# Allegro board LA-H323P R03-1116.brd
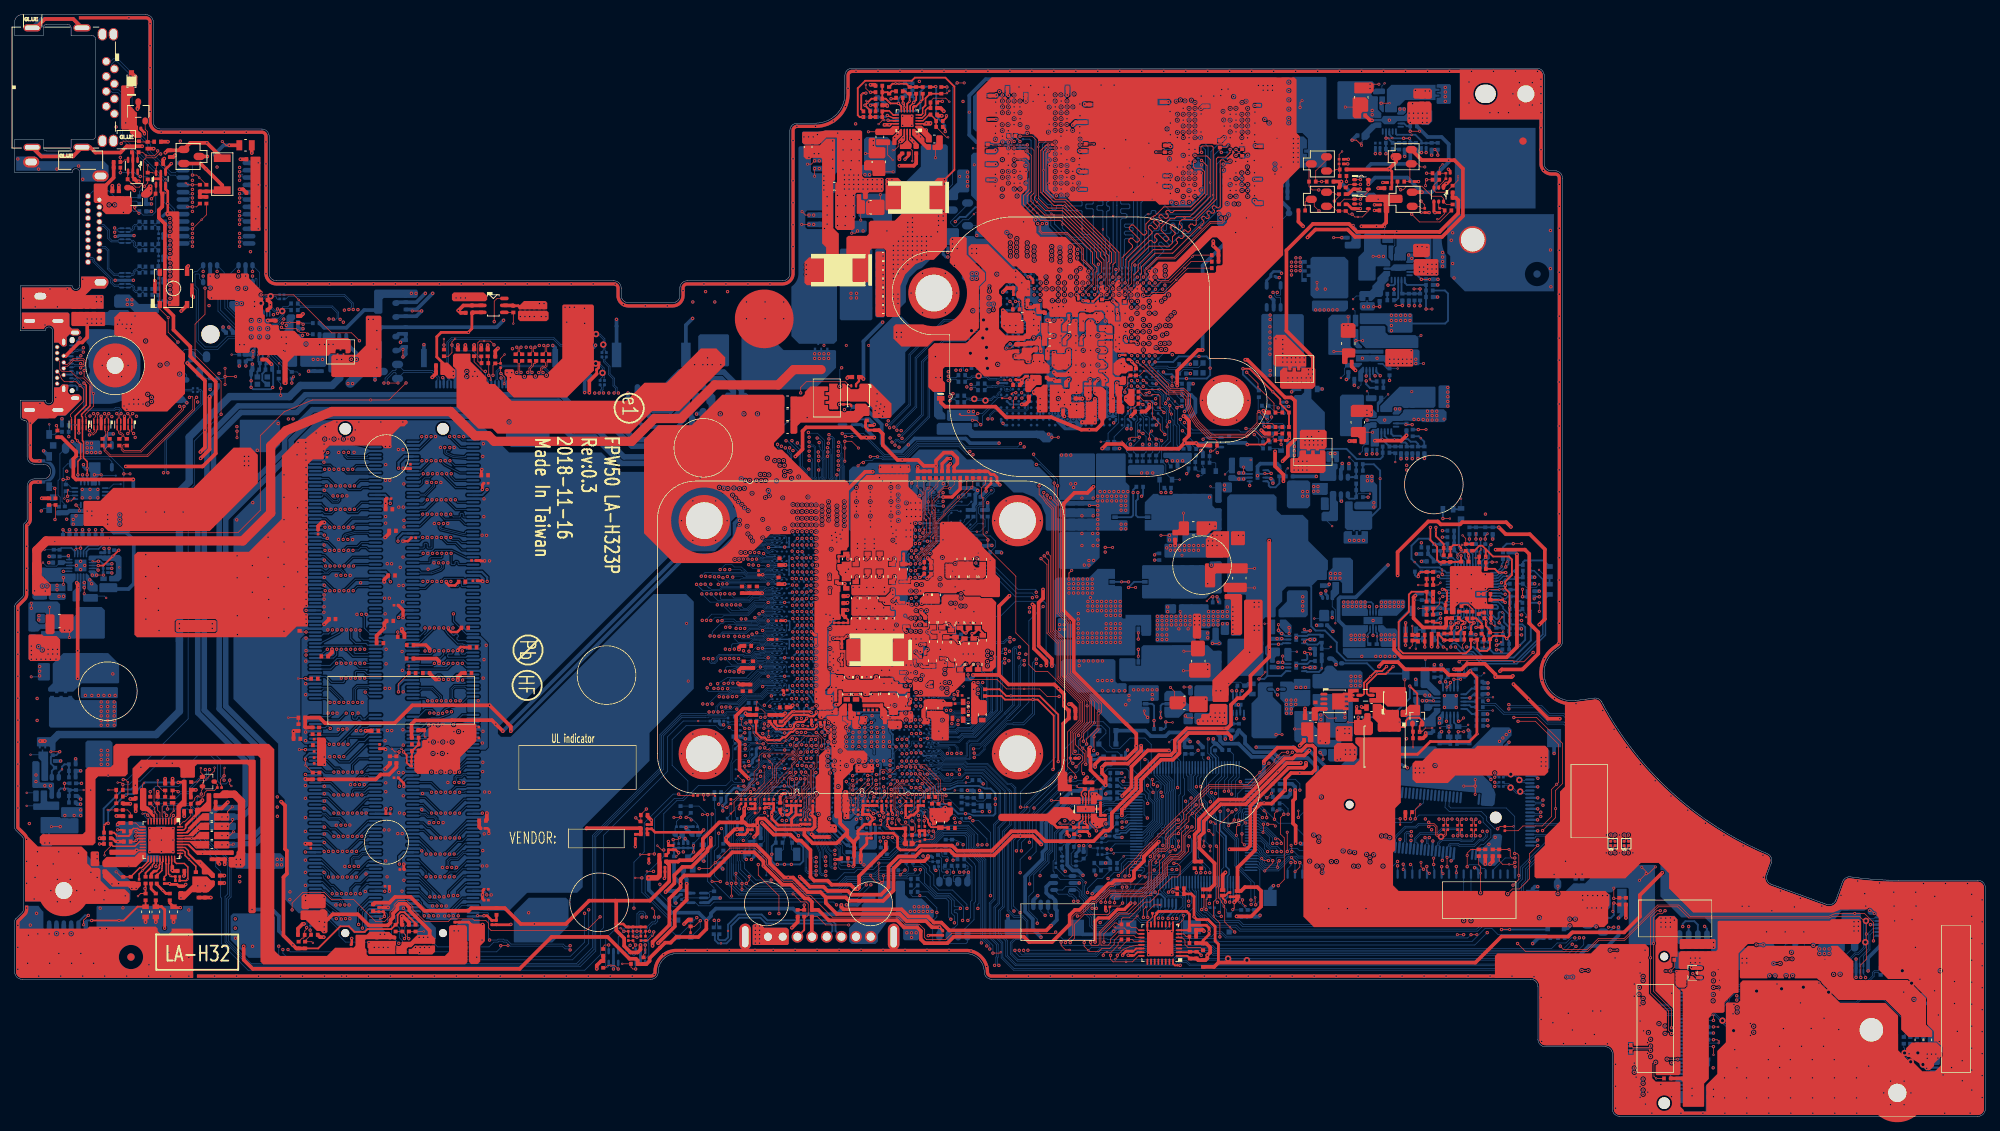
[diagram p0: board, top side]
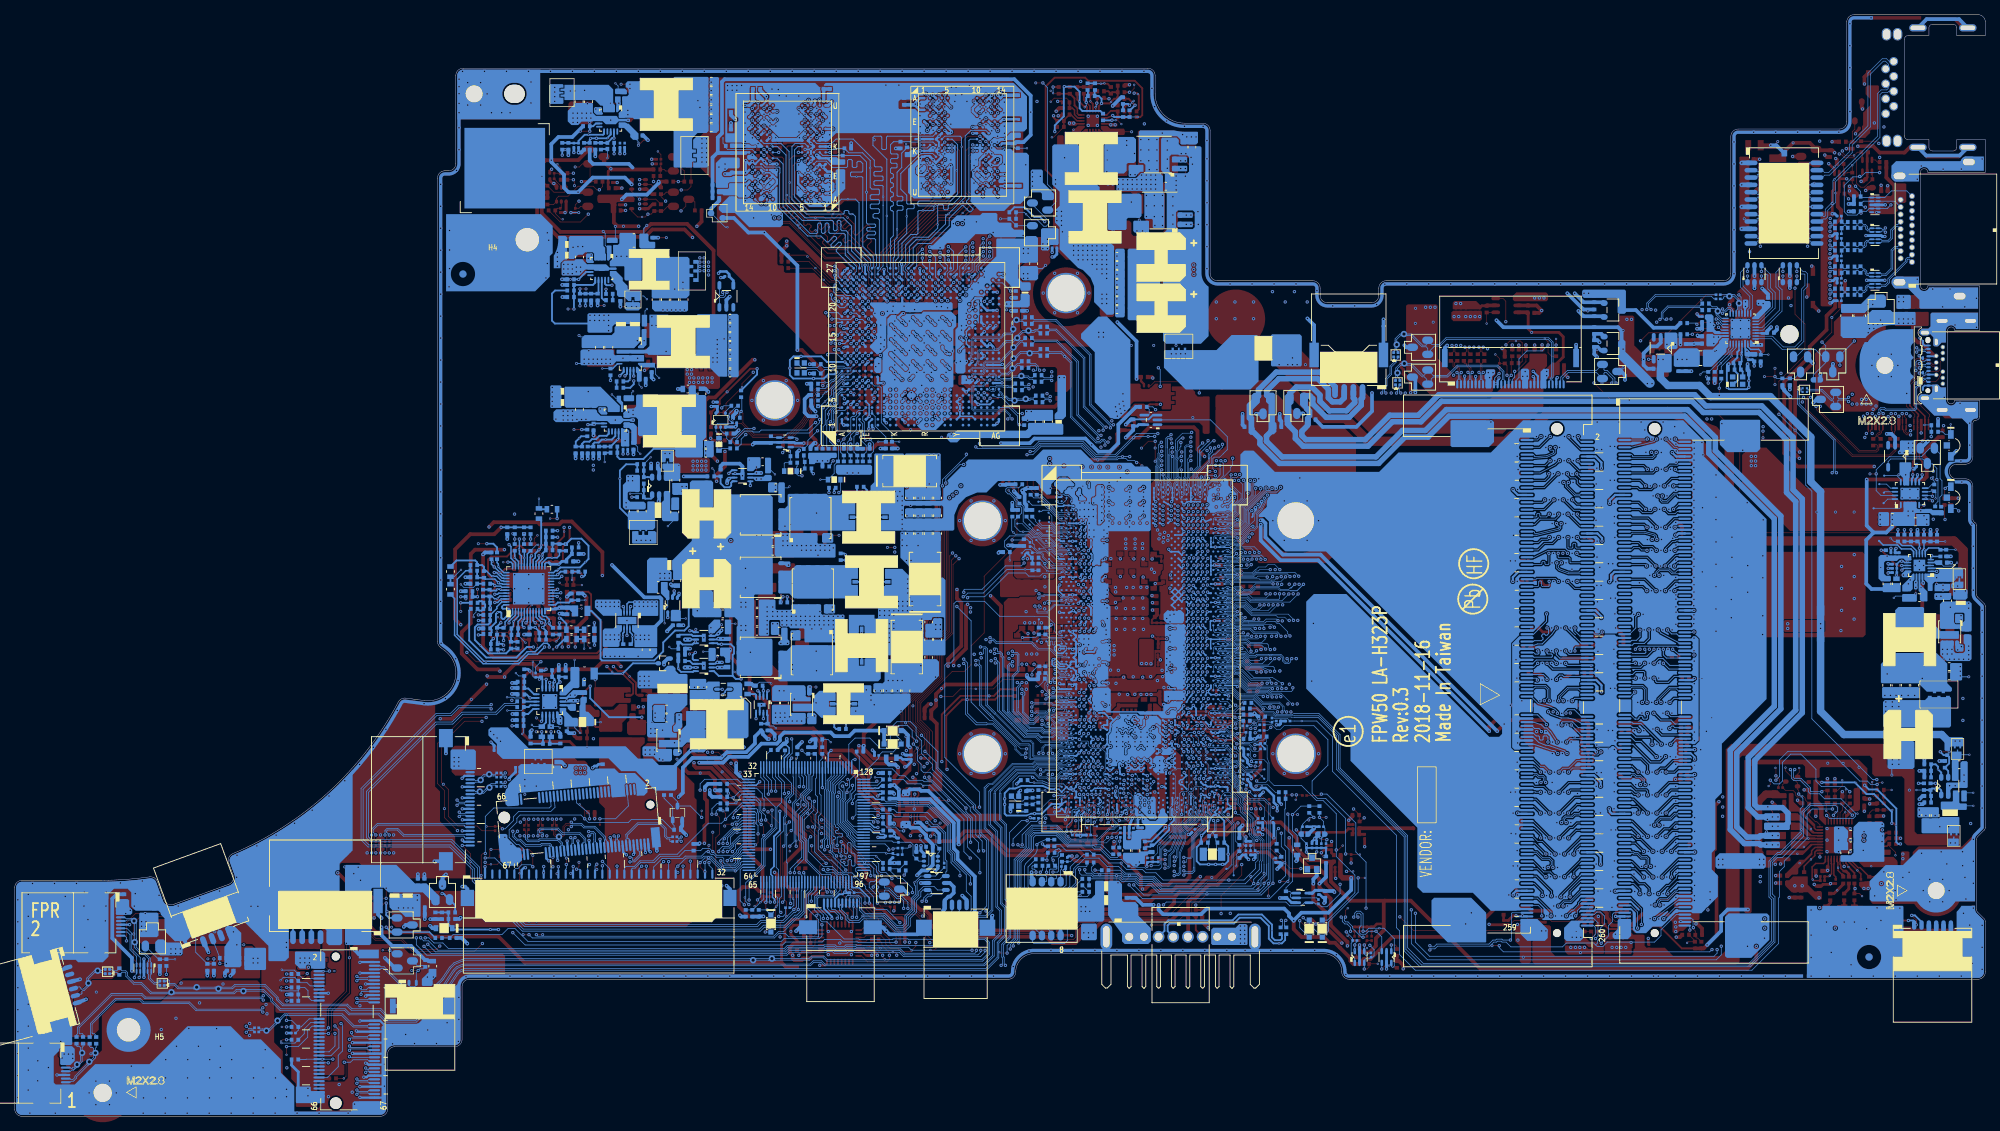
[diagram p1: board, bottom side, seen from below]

Outline 268.7 x 150.3 mm; copper layers: TOP, VCC, IN1, IN2, GND, BOTTOM. Coordinates in mm from the lower left corner of the outline.
Outline path: 0,149.3 0,147.45 3.89,147.45 3.89,148.5 arc(4.04,148.86) 4.39,149 7.19,149 arc(7.54,148.86) 7.69,148.5 7.69,147.45 10.54,147.45 arc(10.89,147.31) 11.04,146.95 11.04,133.75 arc(10.89,133.4) 10.54,133.25 7.69,133.25 7.69,132.2 arc(7.54,131.85) 7.19,131.7 4.39,131.7 arc(4.04,131.85) 3.89,132.2 3.89,133.25 0,133.25 0,128.8 7.85,128.8 arc(8.35,129.3) 8.85,128.8 8.85,113.3 arc(8.35,112.8) 7.85,113.3 0.78,113.3 0.78,107.2 4.17,107.2 arc(4.67,107.7) 5.17,107.2 5.17,97.7 arc(4.67,97.2) 4.17,97.7 0.78,97.7 0.78,95.47 arc(0.93,95.11) 1.29,94.97 arc(1.58,94.86) 1.7,94.57 1.7,89.97 arc(1.99,89.26) 2.7,88.97 3.9,88.97 arc(4.9,87.97) 3.9,86.97 2.7,86.97 arc(1.99,86.68) 1.7,85.97 1.7,81.47 arc(1.63,81.22) 1.45,81.04 arc(1.27,80.85) 1.2,80.6 1.2,71.21 arc(1.16,71.02) 1.05,70.85 0.15,69.95 arc(0.04,69.78) 0,69.59 0,39.41 arc(0.04,39.22) 0.15,39.05 1.05,38.15 arc(1.16,37.98) 1.2,37.79 1.2,28.21 arc(1.16,28.02) 1.05,27.85 0.15,26.95 arc(0.04,26.78) 0,26.59 0,19.7 arc(0.29,18.99) 1,18.7 86.75,18.7 arc(87.46,18.99) 87.75,19.7 arc(88.48,21.47) 90.25,22.2 129.7,22.2 arc(131.47,21.47) 132.2,19.7 arc(132.49,18.99) 133.2,18.7 206.7,18.7 arc(207.41,18.41) 207.7,17.7 207.7,10.5 arc(207.99,9.79) 208.7,9.5 216.85,9.5 arc(217.56,9.21) 217.85,8.5 217.85,1 arc(218.14,0.29) 218.85,0 267.7,0 arc(268.41,0.29) 268.7,1 268.7,31.2 arc(268.41,31.91) 267.7,32.2 256.85,32.2 arc(253.58,32.32) 250.32,32.67 arc(249.66,32.54) 249.23,32.02 248.32,29.51 arc(247.81,28.95) 247.04,28.92 239.52,31.65 arc(238.96,32.17) 238.93,32.93 239.52,34.57 arc(239.5,35.31) 238.97,35.83 arc(225.9,44.24) 216.39,56.54 arc(215.97,56.96) 215.38,57.06 212.83,56.73 arc(208.83,59.05) 210.04,63.52 210.66,63.99 arc(210.95,64.35) 211.05,64.79 211.05,128 arc(210.76,128.71) 210.05,129 209.55,129 arc(208.84,129.29) 208.55,130 208.55,142 arc(208.26,142.71) 207.55,143 114.2,143 arc(113.49,142.71) 113.2,142 113.2,139.5 arc(112.03,136.67) 109.2,135.5 106.7,135.5 arc(105.99,135.21) 105.7,134.5 105.7,115 arc(105.41,114.29) 104.7,114 91.7,114 arc(90.99,113.71) 90.7,113 90.7,112 arc(90.41,111.29) 89.7,111 83.7,111 arc(82.99,111.29) 82.7,112 82.7,113 arc(82.41,113.71) 81.7,114 35.7,114 arc(34.99,114.29) 34.7,115 34.7,133.7 arc(34.41,134.41) 33.7,134.7 19.9,134.7 arc(19.19,134.99) 18.9,135.7 18.9,149.3 arc(18.61,150.01) 17.9,150.3 1,150.3 arc(0.29,150.01) 0,149.3

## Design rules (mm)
net group CLK_PCIE_N3: nets CLK_PCIE_N3 CLK_PCIE_P3
net group CNVI_WGR_CLK_D: nets CNVI_WGR_CLK_DN CNVI_WGR_CLK_DP
net group CNVI_WGR_DATA0_D: nets CNVI_WGR_DATA0_DN CNVI_WGR_DATA0_DP
net group CNVI_WGR_DATA1_D: nets CNVI_WGR_DATA1_DN CNVI_WGR_DATA1_DP
net group CNVI_WT_CLK_D: nets CNVI_WT_CLK_DN CNVI_WT_CLK_DP
net group CNVI_WT_DATA0_D: nets CNVI_WT_DATA0_DN CNVI_WT_DATA0_DP
net group CNVI_WT_DATA1_D: nets CNVI_WT_DATA1_DN CNVI_WT_DATA1_DP
net group D_MIC_: nets D_MIC_CLK D_MIC_DATA
net group DDR5-CLK1: nets FB_CLK1 FB_CLK#1
net group DDR5-WCK01: nets FB_WCK01 FB_WCK01#
net group DDR5-WCK23: nets FB_WCK23 FB_WCK23#
net group DDR5-WCK45: nets FB_WCK45 FB_WCK45#
net group DDR5-WCK67: nets FB_WCK67 FB_WCK67#
net group DDR-CLK0: nets FB_CLK0 FB_CLK#0
net group DIFFPAIR0: nets SPK_L+_CONN SPK_L-_CONN
net group DIFFPAIR1: nets SPK_R+_CONN SPK_R-_CONN
net group DIFFPAIR2: nets EC_SMB_CK2 EC_SMB_DA2
net group DIFFPAIR3: nets EC_SMB_CK1 EC_SMB_DA1
net group EDP_AUX: nets EDP_AUXN EDP_AUXP
net group EDP_AUX_C: nets EDP_AUXN_C EDP_AUXP_C
net group EDP_TX0: nets EDP_TXN0 EDP_TXP0
net group EDP_TX0_C: nets EDP_TXN0_C EDP_TXP0_C
net group EDP_TX1: nets EDP_TXN1 EDP_TXP1
net group EDP_TX1_C: nets EDP_TXN1_C EDP_TXP1_C
net group HDMI_CLK: nets HDMI_CLKN HDMI_CLKP
net group HDMI_R_CLK: nets HDMI_R_CLKN HDMI_R_CLKP
net group HDMI_R_TX_0: nets HDMI_R_TX_N0 HDMI_R_TX_P0
net group HDMI_R_TX_1: nets HDMI_R_TX_N1 HDMI_R_TX_P1
net group HDMI_R_TX_2: nets HDMI_R_TX_N2 HDMI_R_TX_P2
net group HDMI_TX_0: nets HDMI_TX_N0 HDMI_TX_P0
net group HDMI_TX_1: nets HDMI_TX_N1 HDMI_TX_P1
net group HDMI_TX_2: nets HDMI_TX_N2 HDMI_TX_P2
net group HOST_DP1_0: nets HOST_DP1_N0 HOST_DP1_P0
net group HOST_DP1_1: nets HOST_DP1_N1 HOST_DP1_P1
net group HOST_DP1_2: nets HOST_DP1_N2 HOST_DP1_P2
net group HOST_DP1_3: nets HOST_DP1_N3 HOST_DP1_P3
net group HOST_DP1_CTRL_: nets HOST_DP1_CTRL_CLK HOST_DP1_CTRL_DATA
net group I2C0__TP: nets I2C0_SCL_TP I2C0_SDA_TP
net group LAN_MDI0: nets LAN_MDIN0 LAN_MDIP0
net group LAN_MDI1: nets LAN_MDIN1 LAN_MDIP1
net group LAN_MDI2: nets LAN_MDIN2 LAN_MDIP2
net group LAN_MDI3: nets LAN_MDIN3 LAN_MDIP3
net group PCH_RTCX: nets PCH_RTCX1 PCH_RTCX2
net group PCH_SMB: nets PCH_SMBCLK PCH_SMBDATA
net group PCIEPCIE_CRX_DTX_13: nets PCIE_CRX_DTX_N13 PCIE_CRX_DTX_P13
net group PCIEPCIE_CRX_DTX_14: nets PCIE_CRX_DTX_N14 PCIE_CRX_DTX_P14
net group PCIEPCIE_CTX_C_DRX_13: nets PCIE_CTX_C_DRX_N13 PCIE_CTX_C_DRX_P13
net group PCIEPCIE_CTX_C_DRX_14: nets PCIE_CTX_C_DRX_N14 PCIE_CTX_C_DRX_P14
net group PCIEPCIE_CTX_DRX_13: nets PCIE_CTX_DRX_N13 PCIE_CTX_DRX_P13
net group PCIEPCIE_CTX_DRX_14: nets PCIE_CTX_DRX_N14 PCIE_CTX_DRX_P14
net group PCIEPCIE_RCOMP: nets PCIE_RCOMPN PCIE_RCOMPP
net group PECI: nets EC_PECI H_PECI
net group RJ45_MDI0: nets RJ45_MDIN0 RJ45_MDIP0
net group RJ45_MDI1: nets RJ45_MDIN1 RJ45_MDIP1
net group RJ45_MDI2: nets RJ45_MDIN2 RJ45_MDIP2
net group RJ45_MDI3: nets RJ45_MDIN3 RJ45_MDIP3
net group S-10: nets PLT_RST_VGA_HOLD# PLT_RST_VGA_MON#
net group SATA_CRX_C_DTX_0: nets SATA_CRX_C_DTX_N0 SATA_CRX_C_DTX_P0
net group SATA_CRX_DTX_0: nets SATA_CRX_DTX_N0 SATA_CRX_DTX_P0
net group SATA_CTX_C_DRX_0: nets SATA_CTX_C_DRX_N0 SATA_CTX_C_DRX_P0
net group SATA_CTX_DRX_0: nets SATA_CTX_DRX_N0 SATA_CTX_DRX_P0
net group SMB: nets SMBCLK SMBDATA
net group SML0: nets SML0CLK SML0DATA
net group SML1: nets SML1CLK SML1DATA
net group TP_: nets TP_CLK TP_DATA
net group UART: nets UART_2_CRXD_DTXD UART_2_CTXD_DRXD
net group USB2USB20_3_C: nets USB20_N3_C USB20_P3_C
net group USB2USB20_6: nets USB20_N6 USB20_P6
net group USB3_CRX_DTX_1: nets USB3_CRX_DTX_N1 USB3_CRX_DTX_P1
net group USB3_CRX_DTX_2: nets USB3_CRX_DTX_N2 USB3_CRX_DTX_P2
net group USB3_CTX_C_DRX_1: nets USB3_CTX_C_DRX_N1 USB3_CTX_C_DRX_P1
net group USB3_CTX_C_DRX_2: nets USB3_CTX_C_DRX_N2 USB3_CTX_C_DRX_P2
net group USB3_CTX_DRX_1: nets USB3_CTX_DRX_N1 USB3_CTX_DRX_P1
net group USB3_CTX_DRX_2: nets USB3_CTX_DRX_N2 USB3_CTX_DRX_P2
net group USB3USB3_CRX_DTX_3: nets USB3_CRX_DTX_N3 USB3_CRX_DTX_P3
net group USB3USB3_CRX_DTX_4: nets USB3_CRX_DTX_N4 USB3_CRX_DTX_P4
net group USB3USB3_CTX_C_DRX_3: nets USB3_CTX_C_DRX_N3 USB3_CTX_C_DRX_P3
net group USB3USB3_CTX_C_DRX_4: nets USB3_CTX_C_DRX_N4 USB3_CTX_C_DRX_P4
net group USB3USB3_CTX_DRX_3: nets USB3_CTX_DRX_N3 USB3_CTX_DRX_P3
net group USB3USB3_CTX_DRX_4: nets USB3_CTX_DRX_N4 USB3_CTX_DRX_P4
net group USB20_1: nets USB20_N1 USB20_P1
net group USB20_1_R: nets USB20_N1_R USB20_P1_R
net group USB20_2: nets USB20_N2 USB20_P2
net group USB20_2_R: nets USB20_N2_R USB20_P2_R
net group USB20_3: nets USB20_N3 USB20_P3
net group USB20_4_R: nets USB20_N4_R USB20_P4_R
net group USB20_5: nets USB20_N5 USB20_P5
net group USB20_5_R: nets USB20_N5_R USB20_P5_R
net group USB20_7: nets USB20_N7 USB20_P7
net group USB20_7_R: nets USB20_N7_R USB20_P7_R
net group USB20_N10: nets USB20_N10 USB20_P10
net group W15: nets CC1 CC2
net group CNVI: nets CNVI_BRI_DT CNVI_BRI_DT_R CNVI_BRI_RSP CNVI_BRI_RSP_R CNVI_RF_RESET_N CNVI_RF_RESET_R_N CNVI_RGI_DT CNVI_RGI_DT_R CNVI_RGI_RSP CNVI_RGI_RSP_R
net group CRYSTAL: nets XTAL_OUT XTALIN XTLI XTLO
net group DDR_M0(CLK-CMD): nets DDR_M0_ACT# DDR_M0_ALERT# DDR_M0_BA0 DDR_M0_BA1 DDR_M0_BG0 DDR_M0_BG1 DDR_M0_MA0 DDR_M0_MA1 DDR_M0_MA2 DDR_M0_MA3 DDR_M0_MA4 DDR_M0_MA5 DDR_M0_MA6 DDR_M0_MA7 DDR_M0_MA8 DDR_M0_MA9 DDR_M0_MA10 DDR_M0_MA11 DDR_M0_MA12 DDR_M0_MA13 DDR_M0_MA14_WE# DDR_M0_MA15_CAS# DDR_M0_MA16_RAS# DDR_M0_PAR
net group DDR_M0(CLK-CTRL): nets DDR_M0_CKE0 DDR_M0_CKE1 DDR_M0_CS#0 DDR_M0_CS#1 DDR_M0_ODT0 DDR_M0_ODT1
net group DDR_M0(CLK-DQS): nets DDR_M0_CLK0 DDR_M0_CLK1 DDR_M0_CLK#0 DDR_M0_CLK#1
net group DDR_M0-DQ0: nets DDR_M0_D0 DDR_M0_D1 DDR_M0_D2 DDR_M0_D3 DDR_M0_D4 DDR_M0_D5 DDR_M0_D6 DDR_M0_D7 DDR_M0_DQS0 DDR_M0_DQS#0
net group DDR_M0-DQ1: nets DDR_M0_D8 DDR_M0_D9 DDR_M0_D10 DDR_M0_D11 DDR_M0_D12 DDR_M0_D13 DDR_M0_D14 DDR_M0_D15 DDR_M0_DQS1 DDR_M0_DQS#1
net group DDR_M0-DQ2: nets DDR_M0_D16 DDR_M0_D17 DDR_M0_D18 DDR_M0_D19 DDR_M0_D20 DDR_M0_D21 DDR_M0_D22 DDR_M0_D23 DDR_M0_DQS2 DDR_M0_DQS#2
net group DDR_M0-DQ3: nets DDR_M0_D24 DDR_M0_D25 DDR_M0_D26 DDR_M0_D27 DDR_M0_D28 DDR_M0_D29 DDR_M0_D30 DDR_M0_D31 DDR_M0_DQS3 DDR_M0_DQS#3
net group DDR_M0-DQ4: nets DDR_M0_D32 DDR_M0_D33 DDR_M0_D34 DDR_M0_D35 DDR_M0_D36 DDR_M0_D37 DDR_M0_D38 DDR_M0_D39 DDR_M0_DQS4 DDR_M0_DQS#4
net group DDR_M0-DQ5: nets DDR_M0_D40 DDR_M0_D41 DDR_M0_D42 DDR_M0_D43 DDR_M0_D44 DDR_M0_D45 DDR_M0_D46 DDR_M0_D47 DDR_M0_DQS5 DDR_M0_DQS#5
net group DDR_M0-DQ6: nets DDR_M0_D48 DDR_M0_D49 DDR_M0_D50 DDR_M0_D51 DDR_M0_D52 DDR_M0_D53 DDR_M0_D54 DDR_M0_D55 DDR_M0_DQS6 DDR_M0_DQS#6
net group DDR_M0-DQ7: nets DDR_M0_D56 DDR_M0_D57 DDR_M0_D58 DDR_M0_D59 DDR_M0_D60 DDR_M0_D61 DDR_M0_D62 DDR_M0_D63 DDR_M0_DQS7 DDR_M0_DQS#7
net group DDR_M1(CLK-CMD): nets DDR_M1_ACT# DDR_M1_ALERT# DDR_M1_BA0 DDR_M1_BA1 DDR_M1_BG0 DDR_M1_BG1 DDR_M1_MA0 DDR_M1_MA1 DDR_M1_MA2 DDR_M1_MA3 DDR_M1_MA4 DDR_M1_MA5 DDR_M1_MA6 DDR_M1_MA7 DDR_M1_MA8 DDR_M1_MA9 DDR_M1_MA10 DDR_M1_MA11 DDR_M1_MA12 DDR_M1_MA13 DDR_M1_MA14_WE# DDR_M1_MA15_CAS# DDR_M1_MA16_RAS# DDR_M1_PAR
net group DDR_M1(CLK-CTRL): nets DDR_M1_CKE0 DDR_M1_CKE1 DDR_M1_CS#0 DDR_M1_CS#1 DDR_M1_ODT0 DDR_M1_ODT1
net group DDR_M1(CLK-DQS): nets DDR_M1_CLK0 DDR_M1_CLK1 DDR_M1_CLK#0 DDR_M1_CLK#1
net group DDR_M1-DQ0: nets DDR_M1_D0 DDR_M1_D1 DDR_M1_D2 DDR_M1_D3 DDR_M1_D4 DDR_M1_D5 DDR_M1_D6 DDR_M1_D7 DDR_M1_DQS0 DDR_M1_DQS#0
net group DDR_M1-DQ1: nets DDR_M1_D8 DDR_M1_D9 DDR_M1_D10 DDR_M1_D11 DDR_M1_D12 DDR_M1_D13 DDR_M1_D14 DDR_M1_D15 DDR_M1_DQS1 DDR_M1_DQS#1
net group DDR_M1-DQ2: nets DDR_M1_D16 DDR_M1_D17 DDR_M1_D18 DDR_M1_D19 DDR_M1_D20 DDR_M1_D21 DDR_M1_D22 DDR_M1_D23 DDR_M1_DQS2 DDR_M1_DQS#2
net group DDR_M1-DQ3: nets DDR_M1_D24 DDR_M1_D25 DDR_M1_D26 DDR_M1_D27 DDR_M1_D28 DDR_M1_D29 DDR_M1_D30 DDR_M1_D31 DDR_M1_DQS3 DDR_M1_DQS#3
net group DDR_M1-DQ4: nets DDR_M1_D32 DDR_M1_D33 DDR_M1_D34 DDR_M1_D35 DDR_M1_D36 DDR_M1_D37 DDR_M1_D38 DDR_M1_D39 DDR_M1_DQS4 DDR_M1_DQS#4
net group DDR_M1-DQ5: nets DDR_M1_D40 DDR_M1_D41 DDR_M1_D42 DDR_M1_D43 DDR_M1_D44 DDR_M1_D45 DDR_M1_D46 DDR_M1_D47 DDR_M1_DQS5 DDR_M1_DQS#5
net group DDR_M1-DQ6: nets DDR_M1_D48 DDR_M1_D49 DDR_M1_D50 DDR_M1_D51 DDR_M1_D52 DDR_M1_D53 DDR_M1_D54 DDR_M1_D55 DDR_M1_DQS6 DDR_M1_DQS#6
net group DDR_M1-DQ7: nets DDR_M1_D56 DDR_M1_D57 DDR_M1_D58 DDR_M1_D59 DDR_M1_D60 DDR_M1_D61 DDR_M1_D62 DDR_M1_D63 DDR_M1_DQS7 DDR_M1_DQS#7
net group DGPU_PCIE-12: nets PEG_CRX_C_GTX_N5 PEG_CRX_C_GTX_N6 PEG_CRX_C_GTX_N7 PEG_CRX_C_GTX_N8 PEG_CRX_C_GTX_P5 PEG_CRX_C_GTX_P6 PEG_CRX_C_GTX_P7 PEG_CRX_C_GTX_P8 PEG_CRX_GTX_N5 PEG_CRX_GTX_N6 PEG_CRX_GTX_N7 PEG_CRX_GTX_N8 PEG_CRX_GTX_P5 PEG_CRX_GTX_P6 PEG_CRX_GTX_P7 PEG_CRX_GTX_P8 PEG_CTX_C_GRX_N5 PEG_CTX_C_GRX_N6 PEG_CTX_C_GRX_N7 PEG_CTX_C_GRX_N8 PEG_CTX_C_GRX_P5 PEG_CTX_C_GRX_P6 PEG_CTX_C_GRX_P7 PEG_CTX_C_GRX_P8 PEG_CTX_GRX_N5 PEG_CTX_GRX_N6 PEG_CTX_GRX_N7 PEG_CTX_GRX_N8 PEG_CTX_GRX_P5 PEG_CTX_GRX_P6 PEG_CTX_GRX_P7 PEG_CTX_GRX_P8
net group GDDR5_CMD: nets FB_CMD0 FB_CMD1 FB_CMD2 FB_CMD3 FB_CMD4 FB_CMD5 FB_CMD6 FB_CMD7 FB_CMD8 FB_CMD9 FB_CMD10 FB_CMD11 FB_CMD12 FB_CMD13 FB_CMD14 FB_CMD15 FB_CMD16 FB_CMD17 FB_CMD18 FB_CMD19 FB_CMD20 FB_CMD21 FB_CMD22 FB_CMD23 FB_CMD24 FB_CMD25 FB_CMD26 FB_CMD27 FB_CMD28 FB_CMD29 FB_CMD30 FB_CMD31
net group GDDR5_DQ: nets FB_D0 FB_D1 FB_D2 FB_D3 FB_D4 FB_D5 FB_D6 FB_D7 FB_D8 FB_D9 FB_D10 FB_D11 FB_D12 FB_D13 FB_D14 FB_D15 FB_D16 FB_D17 FB_D18 FB_D19 FB_D20 FB_D21 FB_D22 FB_D23 FB_D24 FB_D25 FB_D26 FB_D27 FB_D28 FB_D29 FB_D30 FB_D31 FB_D32 FB_D33 FB_D34 FB_D35 FB_D36 FB_D37 FB_D38 FB_D39 FB_D40 FB_D41 FB_D42 FB_D43 FB_D44 FB_D45 FB_D46 FB_D47 FB_D48 FB_D49 FB_D50 FB_D51 FB_D52 FB_D53 FB_D54 FB_D55 FB_D56 FB_D57 FB_D58 FB_D59 FB_D60 FB_D61 FB_D62 FB_D63
net group GDDR5_EDC/DBI: nets FB_DBI0 FB_DBI1 FB_DBI2 FB_DBI3 FB_DBI4 FB_DBI5 FB_DBI6 FB_DBI7 FB_EDC0 FB_EDC1 FB_EDC2 FB_EDC3 FB_EDC4 FB_EDC5 FB_EDC6 FB_EDC7
net group GUARDRING: nets PCH_XTAL24_IN PCH_XTAL24_IN_R PCH_XTAL24_OUT PCH_XTAL24_OUT_R XCLK_BIASREF
net group HDA: nets EC_BEEP# HDA_RST# HDA_RST#_R HDA_SDIN0 HDA_SDIN0_R HDA_SDOUT HDA_SDOUT_R HDA_SPKR HDA_SYNC HDA_SYNC_R N36039462 PC_BEEP PC_BEEP_R
net group KB: nets KSI0 KSI1 KSI2 KSI3 KSI4 KSI5 KSI6 KSI7 KSO0 KSO1 KSO2 KSO3 KSO4 KSO5 KSO6 KSO7 KSO8 KSO9 KSO10 KSO11 KSO12 KSO13 KSO14 KSO15 KSO16 KSO17
net group PCIE-12: nets PCIE_CRX_C_DTX_N9 PCIE_CRX_C_DTX_P9 PCIE_CRX_DTX_N9 PCIE_CRX_DTX_N10 PCIE_CRX_DTX_N15 PCIE_CRX_DTX_N16 PCIE_CRX_DTX_P9 PCIE_CRX_DTX_P10 PCIE_CRX_DTX_P15 PCIE_CRX_DTX_P16 PCIE_CTX_C_DRX_N9 PCIE_CTX_C_DRX_N10 PCIE_CTX_C_DRX_N15 PCIE_CTX_C_DRX_N16 PCIE_CTX_C_DRX_P9 PCIE_CTX_C_DRX_P10 PCIE_CTX_C_DRX_P15 PCIE_CTX_C_DRX_P16 PCIE_CTX_DRX_N9 PCIE_CTX_DRX_N10 PCIE_CTX_DRX_N15 PCIE_CTX_DRX_N16 PCIE_CTX_DRX_P9 PCIE_CTX_DRX_P10 PCIE_CTX_DRX_P15 PCIE_CTX_DRX_P16
net group PLATFORM CLK: nets CLK_PCIE_N1 CLK_PCIE_N2 CLK_PCIE_P1 CLK_PCIE_P2 CLK_PEG_N0 CLK_PEG_P0
net group S-12: nets EC_VCCST_PG_R H_PROCHOT#_R H_THERMTRIP# PLT_RST# TP_SMBCLK
net group S-15: nets CLK_PCI0 CLK_PCI_LPC CLKIN_XTAL_LCP DGPU_HOLD_RST# EC_KBRST# EC_SPI_CLK EMMC_RCOMP HDA_BIT_CLK HDA_BIT_CLK_R HDMI_CTRL_CLK HOST_SPI_0_CLK I2CA_SCL I2CB_SCL I2CC_SCL I2CS_SCL INT_MIC INT_MIC_R MIC2-VREFO N36039105 PLT_RST#_PCH PLT_RST#_SSD PLT_RST_VGA# PLUG_IN# SCL_CHG SD_RCOMP SM_RCOMP0 SM_RCOMP1 SM_RCOMP2 SPK_L+ SPK_L- SPK_R+ SPK_R- SYS_RESET# USB2_COMP
net group S-20: nets DDR_DRAMRST#
net group S-25: nets EDP_COMP
net group S-30: nets HP_OUTL HP_OUTL_R HP_OUTR HP_OUTR_R HPOUT_L HPOUT_R
net group SMBUS: nets EC_SMB_CK1_R EC_SMB_DA1_R I2CA_SDA I2CB_SDA I2CC_SDA I2CS_SDA SDA_CHG
net group SPI: nets EC_SPI_CS0# EC_SPI_SI EC_SPI_SO HOST_DP1_HPD HOST_SPI_0_CLK_R HOST_SPI_0_CLK_R_TPM HOST_SPI_0_CS0# HOST_SPI_0_CS2# HOST_SPI_0_CS2#_TPM HOST_SPI_0_HOLD# HOST_SPI_0_SI HOST_SPI_0_SI_R HOST_SPI_0_SI_TPM HOST_SPI_0_SIO2 HOST_SPI_0_SIO3 HOST_SPI_0_SO HOST_SPI_0_SO_R HOST_SPI_0_SO_TPM HOST_SPI_0_WP#
net group SVID: nets N19950078 N19950080 SOC_SVID_ALERT# VR_ALERT# VR_SVID_CLK VR_SVID_DATA
net group TP_SMB: nets TP_SMBDATA
net group USB2.0: nets USB20_N4 USB20_N6_R USB20_P4 USB20_P6_R
net group VR: nets RGND_AUXI RGND_SA VSEN_GT
net group W12: nets CFG_RCOMP CPU_POPIRCOMP PCH_OPIRCOMP
net group W20: nets +0.6V_B_VREFDQ +0.6V_DDR_VREFCA +0.6V_VREFCA
nets with their own width: min track width 0.203; nets +3V_SMBUS
nets with their own width: min track width 0.254; nets ECAGND
nets with their own width: min track width 0.305; nets +1.35VS_VRAM
nets with their own width: min track width 0.508; nets 3V_SN +1.8V_PG +3V_LID +3V_PRIM +3V_SPI +3VALW +3VALW_EC +3VL +3VS +3VS_DGPU_AON +3VS_TOUCH +5VALW +5VS +5VS_KBL +5VS_TOUCH +FAN1 +V_DAC GND GNDA LANGND XGND
nets with their own width: min track width 1.016; nets +1.0VS_DGPU +3VS_CAMERA
nets with their own width: min track width 1.524; nets +3VS_SSD +3VS_WLAN +LCDVDD

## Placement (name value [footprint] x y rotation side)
C11  220P_0402_50V7K  [C_0402]  92.24 95.07 180 bottom
C12  220P_0402_50V7K  [C_0402]  95.3 95.07 0 bottom
C13  220P_0402_50V7K  [C_0402]  96.91 94.06 180 bottom
C14  220P_0402_50V7K  [C_0402]  100.1 94.08 0 bottom
C18  0.1U_0201_10V6K  [C_0201]  16.62 134.83 0 top
C19  10P_0402_50V8J  [C_0402]  19.02 132.96 0 top
C117  680P_0402_50V7K  [C_0402]  61.45 103.7 90 top
C118  68P_0402_50V8J  [C_0402]  60.43 103.7 90 top
C140  470P_0402_50V8J  [C_0402]  261.17 10.12 270 bottom
C153  0.01U_0402_16V7K  [C_0402]  258.47 10.82 270 bottom
C154  0.01U_0402_16V7K  [C_0402]  257.58 10.82 270 bottom
C155  0.01U_0402_16V7K  [C_0402]  260.26 10.83 270 bottom
C156  0.01U_0402_16V7K  [C_0402]  259.37 10.83 270 bottom
C174  330U_2.5V_M  [C_MP2VLPS330MC4R2]  10.52 54.89 90 bottom
C193  100P_0402_50V8J  [C_0402]  176.13 37.17 270 bottom
C554  100P_0402_50V8J  [C_0402]  185.72 64.42 270 bottom
C557  680P_0402_50V7K  [C_0402]  184.7 64.42 270 bottom
C570  10U_0402_6.3V6M  [C_0402]  186.74 64.42 270 bottom
C575  10U_0402_6.3V6M  [C_0402]  183.69 64.42 270 bottom
C593  220P_0402_50V7K  [C_0402]  62.64 103.72 90 top
C594  220P_0402_50V7K  [C_0402]  64.5 103.7 90 top
C4801  10U_0402_6.3V6M  [C_0402]  238.87 20.8 270 bottom
C5181  0.1U_0402_25V6  [C_0402]  230.03 3.69 0 bottom
C5182  100P_0402_50V8J  [C_0402]  230.03 2.68 0 bottom
C5183  0.1U_0402_25V6  [C_0402]  228.33 22.22 90 top
C5184  100P_0402_50V8J  [C_0402]  230.03 3.69 0 top
C5185  10P_0402_50V8J  [C_0402]  220.35 8.83 180 top
C5186  10P_0402_50V8J  [C_0402]  220.35 9.71 180 top
C5214  0.1U_0402_16V7K  [C_0402]  239.76 20.8 270 bottom
C5221  .1U_0402_16V7K  [C_0402]  58.36 102.45 180 top
C5222  4.7U_0402_6.3V6M  [C_0402]  58.36 101.48 180 top
C5228  100P_0402_50V8J  [C_0402]  18.13 132.94 270 top
C5230  0.1U_0402_25V6  [C_0402]  171.97 93.15 180 top
C5231  0.1U_0402_16V7K  [C_0402]  62.34 111.54 270 top
C5232  0.1U_0402_16V7K  [C_0402]  62.42 109.62 180 top
C5233  10U_0402_6.3V6M  [C_0402]  187.75 64.42 270 bottom
CA5  0.1U 16V K X7R 0402  [C_0402]  15.98 35.12 90 top
CA6  4.7U_0402_6.3V6M  [C_0402]  15.1 35.12 90 top
CA7  10U_0402_6.3V6M  [C_0402]  14.21 35.12 90 top
CA8  4.7U_0402_6.3V6M  [C_0402]  25.98 33.32 270 top
CA9  0.1U 16V K X7R 0402  [C_0402]  14.8 40.94 270 top
CA10  0.1U 16V K X7R 0402  [C_0402]  25.09 29.85 90 top
CA11  0.1U 16V K X7R 0402  [C_0402]  22.68 31.4 270 top
CA12  0.1U 16V K X7R 0402  [C_0402]  27.96 31.83 180 top
CA13  0.1U 16V K X7R 0402  [C_0402]  11.3 33.35 0 top
CA15  1U_0201_6.3V6K  [C_0201]  20.39 31.75 90 top
CA16  1U_0201_6.3V6K  [C_0201]  22.5 32.72 180 top
CA19  10U_0402_6.3V6M  [C_0402]  27.75 35.98 270 top
CA20  0.1U 16V K X7R 0402  [C_0402]  26.86 35.98 270 top
CA21  10U_0402_6.3V6M  [C_0402]  26.48 42.02 0 top
CA22  0.1U 16V K X7R 0402  [C_0402]  24.97 41.79 90 top
CA23  0.1U 16V K X7R 0402  [C_0402]  24.02 41.62 180 top
CA24  100P_0603_50V7  [C_0603]  17.85 28.61 270 top
CA25  100P_0603_50V7  [C_0603]  19.24 28.61 270 top
CA26  100P_0603_50V7  [C_0603]  21.66 28.61 270 top
CA27  10U_0402_6.3V6M  [C_0402]  24.71 33.32 270 top
CA28  10U_0402_6.3V6M  [C_0402]  19.5 42.69 90 top
CA29  10U_0402_6.3V6M  [C_0402]  14.89 37.49 0 top
CA30  10U_0402_6.3V6M  [C_0402]  15.82 31.77 90 top
CA31  2.2U_0201_6.3V6M  [C_0201]  16.97 31.75 90 top
CA32  4.7U_0402_6.3V6M  [C_0402]  17.42 43.4 180 top
CA33  0.1U 16V K X7R 0402  [C_0402]  17.42 42.38 180 top
CA34  22P 50V J NPO 0402  [C_0402]  20.51 45.38 270 top
CA36  4.7U_0402_6.3V6M  [C_0402]  23.1 44.54 0 top
CA37  0.1U 16V K X7R 0402  [C_0402]  23.1 43.53 0 top
CA39  10U_0402_6.3V6M  [C_0402]  23.14 33.48 180 top
CA41  10P_0402_50V8J  [C_0402]  21.53 44.47 90 top
CA42  0.1U 16V K X7R 0402  [C_0402]  15.82 40.94 270 top
CA43  0.1U 16V K X7R 0402  [C_0402]  14.76 44.53 180 top
CA44  0.1U 16V K X7R 0402  [C_0402]  14.76 43.64 180 top
CA45  10U_0402_6.3V6M  [C_0402]  28.64 35.98 270 top
CA46  10U_0402_6.3V6M  [C_0402]  26.49 42.9 0 top
CA47  10U_0402_6.3V6M  [C_0402]  13.32 35.12 90 top
CA48  1U_0201_6.3V6K  [C_0201]  22.5 32.15 180 top
CC7  1U_0201_6.3V6K  [C_0201]  91.17 37.21 270 bottom
CC8  0.1U_0201_10V6K  [C_0201]  126.55 25.29 270 top
CC9  68P_0201_25V8  [C_0201]  125.98 34.08 180 bottom
CC10  1U_0201_6.3V6K  [C_0201]  92.53 39.52 0 bottom
CC11  1U_0201_6.3V6K  [C_0201]  90.83 39.52 180 bottom
CC12  27P_0402_50V J  [C_0402]  130.77 43.44 90 bottom
CC13  27P_0402_50V J  [C_0402]  130.77 42.58 270 bottom
CC14  0.1U_0201_10V6K  [C_0201]  90.91 30.83 270 bottom
CC15  5.6P_0402_50V  [C_0402]  106 37.34 0 bottom
CC16  5.6P_0402_50V  [C_0402]  104.7 37.34 180 bottom
CC19  0.1U_0201_10V6K  [C_0201]  236 12.09 180 bottom
CC20  0.1U_0201_10V6K  [C_0201]  236 11.51 180 bottom
CC27  10U_0402_6.3V6M  [C_0402]  112.1 71.98 90 top
CC28  10U_0402_6.3V6M  [C_0402]  110.18 57.89 0 top
CC29  1U_0201_6.3V6K  [C_0201]  111.12 72.73 90 top
CC30  1U_0201_6.3V6K  [C_0201]  112.35 76.98 270 top
CC31  1U_0201_6.3V6K  [C_0201]  111.15 70.87 90 top
CC32  1U_0201_6.3V6K  [C_0201]  109.81 55.64 270 top
CC33  1U_0201_6.3V6K  [C_0201]  115.49 54.37 180 top
CC34  1U_0201_6.3V6K  [C_0201]  110.92 59.54 0 top
CC35  1U_0201_6.3V6K  [C_0201]  110.92 60.12 0 top
CC36  1U_0201_6.3V6K  [C_0201]  115.38 53.77 180 top
CC37  10U_0402_6.3V6M  [C_0402]  100.42 64.18 180 top
CC38  10U_0402_6.3V6M  [C_0402]  104.34 55.8 0 top
CC39  10U_0402_6.3V6M  [C_0402]  99.4 62.08 270 top
CC40  10U_0402_6.3V6M  [C_0402]  100.67 62.08 270 top
CC41  10U_0402_6.3V6M  [C_0402]  100.3 57.99 90 top
CC42  10U_0402_6.3V6M  [C_0402]  101.2 72.3 270 top
CC43  1U_0201_6.3V6K  [C_0201]  103.87 67.61 0 top
CC44  1U_0201_6.3V6K  [C_0201]  101.43 74.44 270 top
CC45  1U_0201_6.3V6K  [C_0201]  103.95 65.07 180 top
CC46  1U_0201_6.3V6K  [C_0201]  105.34 58.15 180 top
CC48  1U_0201_6.3V6K  [C_0201]  120.63 53.77 90 top
CC49  .1U_0201_6.3V7K  [C_0201]  86.85 39.22 90 top
CC50  1U_0201_6.3V6K  [C_0201]  88.08 33.99 0 top
CC51  0.1U_0201_10V6K  [C_0201]  114.24 34.63 0 bottom
CC55  1U_0201_6.3V6K  [C_0201]  120 53.77 90 top
CC57  0.1U_0402_16V7K  [C_0402]  116.19 94.18 90 bottom
CC58  10U_0402_6.3V6M  [C_0402]  99.27 58.01 90 top
CC59  10U_0402_6.3V6M  [C_0402]  104.29 76.13 270 top
CC60  10U_0402_6.3V6M  [C_0402]  104.16 73.53 270 top
CC61  1U_0201_6.3V6K  [C_0201]  115.85 55.44 90 top
CC62  0.1U_0201_10V6K  [C_0201]  119.27 53.8 180 top
CC63  1U_0201_6.3V6K  [C_0201]  110.96 54.43 90 top
CC67  1U_0201_6.3V6K  [C_0201]  99.93 39.68 270 top
CC68  1U_0201_6.3V6K  [C_0201]  116.99 55.44 90 top
CC71  0.1U_0201_6.3V6K  [C_0201]  109.23 54.1 180 top
CC72  1U_0201_6.3V6K  [C_0201]  113.27 54.97 0 top
CC73  1U_0201_6.3V6K  [C_0201]  112.47 43.07 0 top
CC74  1U_0201_6.3V6K  [C_0201]  116.19 38.54 270 top
CC76  1U_0201_6.3V6K  [C_0201]  116.42 55.44 90 top
CC80  1U_0201_6.3V6K  [C_0201]  128.23 56.29 180 top
CC81  47U_0805_6.3V6M  [C_0805]  125.1 54.83 90 top
CC82  22U_0603_6.3V6M  [C_0603]  129.33 54.12 0 top
CC86  1U_0201_6.3V6K  [C_0201]  126.35 55.1 90 top
CC87  1U_0201_6.3V6K  [C_0201]  115.55 38.78 90 bottom
CC88  0.1U_0402_25V6  [C_0402]  115.12 100.86 180 top
CC89  0.1U_0201_6.3V  [C_0201]  116.02 94.25 0 top
CC90  0.1U_0201_6.3V  [C_0201]  110.38 55.64 270 top
CC91  1U_0201_6.3V6K  [C_0201]  117.56 55.44 90 top
CC94  1000P_0402_50V7K  [C_0402]  146.92 44.65 90 top
CC95  10P_0402_50V8J  [C_0402]  145.91 44.65 90 top
CC96  0.1U_0201_6.3V  [C_0201]  143.33 45.74 0 top
CC97  1U_0201_6.3V6K  [C_0201]  143.49 39.43 270 top
CC98  1U_0201_6.3V6K  [C_0201]  145.7 39.43 270 top
CC102  1U_0201_6.3V6K  [C_0201]  112.47 43.71 0 top
CC103  1U_0201_6.3V6K  [C_0201]  114.92 38.78 90 bottom
CC111  22U_0603_6.3V6M  [C_0603]  113.45 56.88 90 top
CC112  22U_0603_6.3V6M  [C_0603]  114.72 56.88 90 top
CC115  22U_0603_6.3V6M  [C_0603]  117.08 36.98 270 bottom
CC116  22U_0603_6.3V6M  [C_0603]  115.81 36.98 270 bottom
CC117  1U_0201_6.3V6K  [C_0201]  113.01 97.72 270 top
CC122  100P_0402_50V8J  [C_0402]  200.52 36.42 270 top
CC123  100P_0402_50V8J  [C_0402]  201.53 36.42 270 top
CC127  0.1U_0201_10V6K  [C_0201]  171.28 114.6 0 bottom
CC134  22U_0603_6.3V6M  [C_0603]  129.33 56.53 0 top
CC140  22U_0603_6.3V6M  [C_0603]  182.61 64.35 270 bottom
CC141  0.1U_0201_10V6K  [C_0201]  112.58 55.54 180 top
CC142  1U_0201_6.3V6K  [C_0201]  133.12 87.59 270 top
CC144  22P 50V J NPO 0402  [C_0402]  149.39 46.84 0 bottom
CC154  3.3P_0402_50V8J  [C_0402]  254.43 19.3 90 bottom
CC159  0.1U_0402_25V6  [C_0402]  47.6 22.5 0 top
CC163  0.1U_0402_25V6  [C_0402]  181.47 64.36 270 bottom
CC170  22U_0805_25V6M  [C_0805]  18.91 108.39 90 bottom
CC171  22U_0805_25V6M  [C_0805]  17.13 108.39 90 bottom
CC184  0.22U_0201_6.3V  [C_0201]  178.99 37.5 180 bottom
CC185  0.22U_0201_6.3V  [C_0201]  178.99 38.13 180 bottom
CC186  0.22U_0201_6.3V  [C_0201]  194.83 39.11 90 top
CC187  0.22U_0201_6.3V  [C_0201]  195.4 39.11 90 top
CC256  22P 50V J NPO 0402  [C_0402]  95.41 43.33 0 bottom
CC261  0.1U_0201_6.3V  [C_0201]  145.13 39.43 270 top
CC269  0.1U_0201_10V6K  [C_0201]  113.88 53.79 90 top
CC270  0.1U_0201_10V6K  [C_0201]  129.18 57.42 180 top
CC274  1U_0201_6.3V6K  [C_0201]  148.7 40.49 90 top
CC275  0.1U_0201_6.3V  [C_0201]  148.06 43.37 270 top
CC276  0.22U_0402_16V7K  [C_0402]  129.47 98.32 180 bottom
CC277  0.22U_0402_16V7K  [C_0402]  132.27 99.08 180 bottom
CC278  0.22U_0402_16V7K  [C_0402]  132.27 99.97 180 bottom
CC279  0.22U_0402_16V7K  [C_0402]  129.6 100.22 180 bottom
CC280  0.22U_0402_16V7K  [C_0402]  129.6 101.11 180 bottom
CC281  0.22U_0402_16V7K  [C_0402]  129.47 97.43 180 bottom
CC282  0.22U_0402_16V7K  [C_0402]  131.38 103.02 180 bottom
CC283  0.22U_0402_16V7K  [C_0402]  131.38 102.13 180 bottom
CC288  0.22U_0201_6.3V  [C_0201]  197.3 39.11 90 top
CC289  0.22U_0201_6.3V  [C_0201]  196.73 39.11 90 top
CC290  0.22U_0201_6.3V  [C_0201]  198.64 39.11 90 top
CC291  0.22U_0201_6.3V  [C_0201]  199.21 39.11 90 top
CC292  100P_0402_50V8J  [C_0402]  131.09 77.82 90 bottom
CC293  0.1U_0402_16V7K  [C_0402]  124.94 75.61 180 top
CC295  10P_0402_50V8J  [C_0402]  127.81 36.84 90 bottom
CC296  22P_0201_25V8  [C_0201]  94.81 53.93 0 bottom
CC297  10P_0402_50V8J  [C_0402]  95.99 34.49 90 bottom
CC298  0.1U_0402_16V7K  [C_0402]  101.15 51.5 180 bottom
CC299  0.1U_0402_16V7K  [C_0402]  97.99 51.81 0 bottom
CC300  0.1U_0402_16V7K  [C_0402]  95.36 30.7 270 bottom
CC301  0.1U_0402_16V7K  [C_0402]  121.45 39.26 0 top
CC302  0.1U_0402_16V7K  [C_0402]  122.36 38.37 180 top
CC303  0.1U_0402_16V7K  [C_0402]  128.16 65.75 90 bottom
CC312  22P 50V J NPO 0402  [C_0402]  100.24 54.82 0 bottom
CC314  1.8P_0402_50V8J  [C_0402]  114.46 35.58 0 top
CC315  1.8P_0402_50V8J  [C_0402]  90.04 30.74 270 bottom
CC316  1U_0201_6.3V6K  [C_0201]  110.42 53.77 180 top
CC317  47U_0603_6.3V6M  [C_0603]  131.94 54.06 90 top
CC318  4.7U_0603_10V6K  [C_0603]  126.22 39.39 90 top
CC319  1U_0201_6.3V6K  [C_0201]  124.72 39.9 0 top
CC320  4.7U_0402_6.3V6M  [C_0402]  113.65 36.99 270 bottom
CC321  1U_0201_6.3V6K  [C_0201]  86.22 39.22 90 top
CC323  1U_0201_6.3V6K  [C_0201]  89.14 36.37 90 top
CC324  0.1U_0201_10V6K  [C_0201]  91.8 37.21 270 bottom
CC325  4.7U_0402_6.3V6M  [C_0402]  110.98 38.11 90 top
CC326  0.1U_0201_10V6K  [C_0201]  36.14 112.1 0 bottom
CC327  0.1U_0201_10V6K  [C_0201]  36.14 111.53 0 bottom
CC328  1U_0201_6.3V6K  [C_0201]  113.27 55.54 0 top
CC329  22U_0603_6.3V6M  [C_0603]  129.33 55.33 0 top
CC331  1U_0201_6.3V6K  [C_0201]  88.08 33.36 0 top
CC332  1U_0201_6.3V6K  [C_0201]  100.57 39.68 270 top
CC333  1U_0201_6.3V6K  [C_0201]  113.27 56.11 0 top
CC334  1U_0201_6.3V6K  [C_0201]  112.47 41.8 0 top
CC335  1U_0201_6.3V6K  [C_0201]  112.47 42.44 0 top
CC336  1U_0201_6.3V6K  [C_0201]  116.82 38.54 270 top
CC337  1U_0201_6.3V6K  [C_0201]  116.15 38.06 0 bottom
CC338  1U_0201_6.3V6K  [C_0201]  116.15 38.69 0 bottom
CC339  1U_0201_6.3V6K  [C_0201]  146.29 39.43 270 top
CC341  1U_0201_6.3V6K  [C_0201]  148.06 40.49 90 top
CC342  1U_0201_6.3V6K  [C_0201]  89.77 36.37 90 top
CC343  1U_0201_6.3V6K  [C_0201]  112.58 54.97 180 top
CC346  10U_0402_6.3V6M  [C_0402]  143.72 54.33 0 top
CC347  10U_0402_6.3V6M  [C_0402]  112.34 68.12 0 top
CC348  10U_0402_6.3V6M  [C_0402]  112.09 70.97 0 top
CC349  10U_0402_6.3V6M  [C_0402]  112.06 70.02 0 top
CC350  10U_0402_6.3V6M  [C_0402]  112.02 69.07 0 top
CC351  1U_0201_6.3V6K  [C_0201]  115.06 54.97 180 top
CC352  0.1U_0201_10V6K  [C_0201]  172.66 92.22 0 top
CC353  0.1U_0201_10V6K  [C_0201]  170.84 94.62 180 bottom
CC354  0.1U_0402_16V7K  [C_0402]  92.16 26.83 270 top
CC355  100P_0402_50V8J  [C_0402]  26.65 99.77 90 bottom
CC356  10U_0402_6.3V6M  [C_0402]  100.19 72.3 270 top
CC357  10U_0402_6.3V6M  [C_0402]  99.17 72.3 270 top
CC358  10U_0402_6.3V6M  [C_0402]  143.72 55.34 0 top
CC359  0.1U_0402_16V7K  [C_0402]  85.38 41.1 0 top
CC360  0.1U_0201_10V6K  [C_0201]  154.25 30.51 0 bottom
CC361  0.1U_0201_10V6K  [C_0201]  149.31 28.58 180 top
CC362  0.1U_0201_10V6K  [C_0201]  148.19 37.38 90 bottom
CC363  0.1U_0201_10V6K  [C_0201]  150.88 49.23 0 bottom
CC364  0.1U_0201_10V6K  [C_0201]  143.96 48.85 0 top
CC365  0.1U_0201_10V6K  [C_0201]  148.95 35.87 270 bottom
CC366  0.1U_0201_10V6K  [C_0201]  84.63 37.89 90 top
CD1  0.1U_0201_10V6K  [C_0201]  65.06 26.14 90 top
CD2  2.2U_0201_6.3V6M  [C_0201]  65.69 26.14 90 top
CD3  10U_0402_6.3V6M  [C_0402]  49.41 21.5 90 top
CD4  10U_0402_6.3V6M  [C_0402]  50.43 21.5 90 top
CD5  1U_0201_6.3V6K  [C_0201]  49.39 24.32 270 top
CD6  1U_0201_6.3V6K  [C_0201]  51.8 24.32 270 top
CD7  10U_0402_6.3V6M  [C_0402]  53.16 22.5 0 top
CD8  10U_0402_6.3V6M  [C_0402]  52.32 22.5 180 top
CD9  1U_0201_6.3V6K  [C_0201]  41.92 27.98 90 top
CD10  0.1U_0402_25V6  [C_0402]  38.84 66.24 90 top
CD11  0.1U_0201_10V6K  [C_0201]  54.69 49.06 180 top
CD12  2.2U_0201_6.3V6M  [C_0201]  54.68 48.42 180 top
CD13  0.1U_0201_10V6K  [C_0201]  52.3 69.72 180 top
CD14  0.1U_0201_10V6K  [C_0201]  54.71 47.77 180 top
CD15  0.022U_0402_25V7K  [C_0402]  54.11 52.68 0 top
CD16  10U_0402_6.3V6M  [C_0402]  61.84 66.65 180 top
CD17  10U_0402_6.3V6M  [C_0402]  51.86 73.79 180 top
CD18  10U_0402_6.3V6M  [C_0402]  61.46 72.94 180 top
CD19  10U_0402_6.3V6M  [C_0402]  41.82 62.76 0 top
CD20  10U_0402_6.3V6M  [C_0402]  62.29 60.47 180 top
CD21  10U_0402_6.3V6M  [C_0402]  43.75 67.84 180 top
CD22  10U_0402_6.3V6M  [C_0402]  62.98 63.98 180 top
CD23  10U_0402_6.3V6M  [C_0402]  51.62 67.58 180 top
CD24  1U_0201_6.3V6K  [C_0201]  49.76 50.74 270 top
CD25  1U_0201_6.3V6K  [C_0201]  51.72 46.2 0 top
CD26  1U_0201_6.3V6K  [C_0201]  50.49 31.39 0 top
CD27  1U_0201_6.3V6K  [C_0201]  51.2 41.3 180 top
CD28  1U_0201_6.3V6K  [C_0201]  42.57 89.94 180 top
CD29  1U_0201_6.3V6K  [C_0201]  41.37 79.43 90 top
CD30  1U_0201_6.3V6K  [C_0201]  63.54 39.3 0 top
CD31  1U_0201_6.3V6K  [C_0201]  64.58 29.49 180 top
CD60  0.1U_0201_10V6K  [C_0201]  49.64 27.92 90 top
CD61  2.2U_0201_6.3V6M  [C_0201]  50.27 28.51 270 top
CD62  10U_0402_6.3V6M  [C_0402]  61.37 25.31 0 top
CD63  10U_0402_6.3V6M  [C_0402]  61.37 24.36 0 top
CD64  1U_0201_6.3V6K  [C_0201]  61.53 23.6 0 top
CD65  1U_0201_6.3V6K  [C_0201]  60 25.9 90 top
CD66  10U_0402_6.3V6M  [C_0402]  39.6 27.8 90 top
CD67  10U_0402_6.3V6M  [C_0402]  40.87 27.8 90 top
CD68  1U_0201_6.3V6K  [C_0201]  57.07 23.68 270 top
CD69  0.1U_0201_10V6K  [C_0201]  41.42 51.46 180 top
CD70  2.2U_0201_6.3V6M  [C_0201]  41.43 48.15 180 top
CD71  0.1U_0201_10V6K  [C_0201]  40.37 37.18 270 top
CD72  0.1U_0201_10V6K  [C_0201]  41.42 49.78 180 top
CD73  10U_0402_6.3V6M  [C_0402]  55.66 60.47 0 top
CD74  10U_0402_6.3V6M  [C_0402]  53.44 62.46 0 top
CD75  10U_0402_6.3V6M  [C_0402]  53.47 64.3 0 top
CD76  10U_0402_6.3V6M  [C_0402]  49.59 52.6 180 top
CD77  10U_0402_6.3V6M  [C_0402]  51.99 79.88 180 top
CD78  10U_0402_6.3V6M  [C_0402]  38.94 51.51 180 top
CD79  10U_0402_6.3V6M  [C_0402]  50.26 64.56 180 top
CD80  10U_0402_6.3V6M  [C_0402]  51.49 82.82 180 top
CD81  0.1U_0201_10V6K  [C_0201]  41.42 48.94 180 top
CD82  0.022U_0402_25V7K  [C_0402]  39.6 54.39 180 top
CD83  1U_0201_6.3V6K  [C_0201]  64.56 86.37 180 top
CD84  1U_0201_6.3V6K  [C_0201]  51.32 84.28 180 top
CD85  1U_0201_6.3V6K  [C_0201]  54.67 78.93 180 top
CD86  1U_0201_6.3V6K  [C_0201]  62.48 73.06 0 top
CD87  1U_0201_6.3V6K  [C_0201]  52.52 33.68 0 top
CD88  1U_0201_6.3V6K  [C_0201]  63.29 51.63 180 top
CD89  1U_0201_6.3V6K  [C_0201]  53.96 88.96 270 top
CD90  1U_0201_6.3V6K  [C_0201]  63.27 53.1 180 top
CD92  0.1U_0402_25V6  [C_0402]  52.23 65.43 0 top
CD93  10U_0402_6.3V6M  [C_0402]  64.54 87.47 180 top
CD94  1U_0201_6.3V6K  [C_0201]  62.3 75.84 0 top
CD95  10U_0402_6.3V6M  [C_0402]  63.34 40.35 0 top
CD96  1U_0201_6.3V6K  [C_0201]  64.58 30.98 180 top
CD97  1U_0201_6.3V6K  [C_0201]  51.16 24.32 270 top
CD98  1U_0201_6.3V6K  [C_0201]  45.87 22.84 90 top
CD99  1U_0201_6.3V6K  [C_0201]  60.64 25.9 90 top
CD100  1U_0201_6.3V6K  [C_0201]  61.53 22.96 0 top
CE24  0.01U_0402_25V7K  [C_0402]  242.43 20.8 270 bottom
CG1  0.1U_0201_10V6K  [C_0201]  68.94 110.31 270 top
CG2  4.7U_0402_6.3V6M  [C_0402]  78.71 102.71 0 top
CG3  0.1U_0201_10V6K  [C_0201]  78.77 101.87 0 top
CG4  1U_0201_6.3V6K  [C_0201]  69.58 110.31 270 top
CG8  0.1U_0402_16V7K  [C_0402]  20.51 112.03 180 bottom
CG9  0.1U_0402_16V7K  [C_0402]  20.51 112.92 180 bottom
CG10  0.1U_0402_16V7K  [C_0402]  20.51 115.08 180 bottom
CG11  0.1U_0402_16V7K  [C_0402]  20.51 115.97 180 bottom
CG12  0.1U_0402_16V7K  [C_0402]  20.51 121.18 180 bottom
CG13  0.1U_0402_16V7K  [C_0402]  20.51 122.07 180 bottom
CG14  0.1U_0402_16V7K  [C_0402]  20.51 118.13 180 bottom
CG15  0.1U_0402_16V7K  [C_0402]  20.51 119.02 180 bottom
CG46  0.1U_0402_16V7K  [C_0402]  13.32 125.29 90 top
CG47  4.7U_0402_6.3V6M  [C_0402]  14.21 125.29 90 top
CG71  180 +-5% 0402  [R_0402]  17.03 119.03 270 bottom
CG72  180 +-5% 0402  [R_0402]  17.03 112.02 90 bottom
CG73  180 +-5% 0402  [R_0402]  17.03 115.98 270 bottom
CG74  180 +-5% 0402  [R_0402]  17.03 122.08 270 bottom
CG75  1U_0201_6.3V6K  [C_0201]  70.21 110.31 270 top
CG76  1U_0201_6.3V6K  [C_0201]  71.55 110.29 270 top
CG77  1U_0201_6.3V6K  [C_0201]  72.18 110.29 270 top
CG78  1U_0201_6.3V6K  [C_0201]  70.85 110.29 270 top
CK1  0.1U_0201_10V6K  [C_0201]  147.07 48.7 90 bottom
CK2  0.1U_0201_10V6K  [C_0201]  146.46 48.71 90 bottom
CK3  0.1U_0201_10V6K  [C_0201]  165.72 29.95 90 top
CK4  0.1U_0402_25V6  [C_0402]  159.61 49.45 90 bottom
CK5  0.1U_0402_16V7K  [C_0402]  172.47 43.58 180 bottom
CK8  4.7U_0402_6.3V6M  [C_0402]  150.3 44.19 180 bottom
CK9  22P 50V J NPO 0402  [C_0402]  159.51 51.43 180 bottom
CK10  0.1U_0402_25V6  [C_0402]  150.3 39.96 180 bottom
CK11  0.1U_0201_10V6K  [C_0201]  149.93 38.23 180 bottom
CL1  0.01U_0402_16V7K  [C_0402]  31.61 126 0 top
CL2  10P_1808_3KV  [C_1808]  28.3 130.72 270 top
CL3  120P_0402_50V8J  [C_0402]  21.19 131.8 270 top
CL4  0.1U_0402_16V7K  [C_0402]  32.52 130.58 180 top
CL5  0.1U_0402_16V7K  [C_0402]  33.79 104.17 270 top
CL8  4.7U_0402_6.3V6M  [C_0402]  41.85 102.58 270 bottom
CL9  0.1U_0402_16V7K  [C_0402]  33.56 110 0 top
CL10  4.7U_0402_6.3V6M  [C_0402]  37.71 105.42 0 bottom
CL11  0.1U_0402_16V7K  [C_0402]  31.52 103.92 270 bottom
CL12  0.1U_0402_16V7K  [C_0402]  29.62 110.76 90 bottom
CL13  0.1U_0402_16V7K  [C_0402]  37.71 107.45 0 bottom
CL14  0.1U_0402_16V7K  [C_0402]  37.71 108.34 0 bottom
CL15  1U_0201_6.3V6K  [C_0201]  38.02 109.11 0 bottom
CL16  0.1U_0402_16V7K  [C_0402]  37.69 106.42 0 bottom
CL19  4.7U_0402_6.3V6M  [C_0402]  35.56 107.62 90 top
CL20  4.7U_0402_6.3V6M  [C_0402]  33.56 111.4 0 top
CL23  0.1U_0402_16V7K  [C_0402]  40.83 102.58 270 bottom
CL24  10P_0402_50V8J  [C_0402]  32.42 101.87 0 bottom
CL25  10P_0402_50V8J  [C_0402]  35.11 101.87 180 bottom
CL26  0.1U_0402_16V7K  [C_0402]  29.74 106.92 180 bottom
CL27  1U_0201_6.3V6K  [C_0201]  32.32 103.81 270 bottom
CL28  1500P_0402_50V7K  [C_0402]  44.31 101.99 0 bottom
CL29  4.7U_0402_6.3V6M  [C_0402]  40.83 104.46 90 bottom
CLED1  0.1U_0402_16V7K  [C_0402]  4.68 83.41 90 top
CLED2  0.1U_0402_16V7K  [C_0402]  7.36 94.28 180 bottom
CLRP1  SHORT PADS  [SHORTPADS]  92.82 38.5 0 bottom
CLRP2  SHORT PADS  [SHORTPADS]  90.53 38.5 180 bottom
CLRP3  SHORT PADS  [SHORTPADS]  121.9 37.23 180 top
CM17  220P_0402_50V7K  [C_0402]  17 125.5 0 bottom
CM26  10P_0402_50V8J  [C_0402]  17 123.46 0 bottom
CM27  10P_0402_50V8J  [C_0402]  17 124.48 0 bottom
CN3  0.1U_0402_16V7K  [C_0402]  227.44 22.22 90 top
CN4  10U_0402_6.3V6M  [C_0402]  229.22 22.22 90 top
CN5  10U_0402_6.3V6M  [C_0402]  230.11 22.22 90 top
CR11  0.1U_0402_10V7K  [C_0402]  38.6 110.89 180 bottom
CR13  0.1U_0402_10V7K  [C_0402]  38.6 110 180 bottom
CS1  0.1U_0201_10V6K  [C_0201]  202.39 46.27 0 bottom
CS2  0.1U_0201_10V6K  [C_0201]  202.39 46.84 0 bottom
CS8  0.1U_0201_10V6K  [C_0201]  199.81 46.98 0 bottom
CS9  1U_0201_6.3V6K  [C_0201]  189.33 47.21 90 bottom
CS10  10P_0201_50V  [C_0201]  199.81 47.62 0 bottom
CS16  VARIST_ CK0402101V05 0402  [CK0402101V05_0402-2]  177.87 39.1 0 bottom
CS23  0.1U_0201_10V6K  [C_0201]  202.39 45.57 0 bottom
CS24  0.1U_0201_10V6K  [C_0201]  202.39 45 0 bottom
CS27  47U_0603_6.3V6M  [C_0603]  194.67 46.93 90 bottom
CS31  0.1U_0402_16V7K  [C_0402]  15.29 92.43 270 top
CS32  0.1U_0402_16V7K  [C_0402]  14.27 92.43 270 top
CS33  0.1U_0402_16V7K  [C_0402]  12.95 92.43 270 top
CS34  0.1U_0402_16V7K  [C_0402]  11.98 92.43 270 top
CSS5  18P_0201_50V NPO  [C_0201]  202.75 49.89 0 bottom
CSS6  10P_0201_50V  [C_0201]  202.75 50.53 0 bottom
CSS7  10U_0402_6.3V6M  [C_0402]  188.53 47.12 90 bottom
CT1  0.1U_0402_16V4Z  [C_0402]  161.15 21.53 90 top
CT2  1U_0201_6.3V6K  [C_0201]  152.38 22.54 270 top
CT3  0.1U_0402_16V4Z  [C_0402]  160.26 21.53 90 top
CT4  0.1U_0402_16V4Z  [C_0402]  160.18 25.42 0 top
CT5  1U_0201_6.3V6K  [C_0201]  155.72 27.71 180 top
CT97  .1U_0402_16V7K  [C_0402]  70.21 103.98 270 top
CT98  .1U_0402_16V7K  [C_0402]  71.1 103.98 270 top
CT100  .1U_0402_16V7K  [C_0402]  71.99 103.98 270 top
CT101  .1U_0402_16V7K  [C_0402]  68.31 103.98 270 top
CT102  .1U_0402_16V7K  [C_0402]  69.2 103.98 270 top
CT103  .1U_0402_16V7K  [C_0402]  72.88 103.98 270 top
CTS1  0.1U_0402_16V4Z  [C_0402]  53.32 107.67 270 bottom
CTS3  4.7U_0402_6.3V6M  [C_0402]  53.32 109.16 90 bottom
CTS6  4.7U_0402_6.3V6M  [C_0402]  53.32 104.97 90 bottom
CTS7  0.1U_0402_16V4Z  [C_0402]  53.32 111.98 270 bottom
CU3  10U_0603_10V6M  [C_0603]  8.81 81.11 0 bottom
CU4  0.1U_0201_10V6K  [C_0201]  9.22 82 0 bottom
CU6  1000P_0402_50V7K  [C_0402]  11.67 109.49 90 bottom
CU7  0.1U_0402_25V6  [C_0402]  10.78 109.49 90 bottom
CU8  0.47U_0402_25V6K  [C_0402]  8.11 110.41 270 top
CU9  0.47U_0402_25V6K  [C_0402]  9 109.49 90 top
CU10  0.47U_0402_25V6K  [C_0402]  9.89 110.41 270 top
CU11  0.47U_0402_25V6K  [C_0402]  10.78 109.49 90 top
CU12  0.1U_0201_10V6K  [C_0201]  10.31 88.29 180 bottom
CU13  47U_0805_6.3V6M  [C_0805]  13.53 81.43 180 bottom
CV2  4.7U_0402_6.3V6M  [C_0402]  138.14 112.23 270 top
CV3  4.7U 6.3V M X5R 0402  [C_0402]  133.38 119.45 90 bottom
CV4  4.7U 6.3V M X5R 0402  [C_0402]  138.29 99.11 270 top
CV5  4.7U 6.3V M X5R 0402  [C_0402]  139.66 100.1 270 top
CV6  4.7U_0402_6.3V6M  [C_0402]  138.52 105.42 270 top
CV7  22U_0603_6.3V6M  [C_0603]  129.76 117.04 270 bottom
CV8  10U_0402_6.3V6M  [C_0402]  138.16 108.05 180 top
CV10  22U_0603_6.3V6M  [C_0603]  138.11 109.1 180 top
CV11  0.22U_0402_16V7K  [C_0402]  127.92 103.78 0 bottom
CV12  0.22U_0402_16V7K  [C_0402]  127.92 104.67 0 bottom
CV13  0.22U_0402_16V7K  [C_0402]  130.01 106.19 0 bottom
CV14  0.22U_0402_16V7K  [C_0402]  130.01 105.3 0 bottom
CV15  0.22U_0402_16V7K  [C_0402]  127.92 106.83 0 bottom
CV16  0.22U_0402_16V7K  [C_0402]  127.92 107.72 0 bottom
CV17  0.22U_0402_16V7K  [C_0402]  130.01 108.12 0 bottom
CV18  0.22U_0402_16V7K  [C_0402]  130.01 109.01 0 bottom
CV20  10U_0402_6.3V6M  [C_0402]  137.27 102.66 90 top
CV22  10U_0402_6.3V6M  [C_0402]  131.31 110.82 270 bottom
CV30  10U_0402_6.3V6M  [C_0402]  130.16 94.3 90 bottom
CV31  0.1U_0201_10V K X5R  [C_0201]  147.27 99.34 90 top
CV34  0.1U_0201_10V K X5R  [C_0201]  146.64 99.34 90 top
CV35  22U_0603_6.3V6M  [C_0603]  127.74 94.06 90 bottom
CV38  4.7U_0402_6.3V6M  [C_0402]  141.38 109.62 180 top
CV44  10U_0402_6.3V6M  [C_0402]  140.47 110.59 180 top
CV45  10U_0402_6.3V6M  [C_0402]  151.32 108.86 180 top
CV46  10U_0402_6.3V6M  [C_0402]  150.29 107.21 180 top
CV51  10U_0402_6.3V6M  [C_0402]  132.19 110.82 270 bottom
CV52  0.1U_0201_10V K X5R  [C_0201]  150.3 110.12 90 top
CV53  0.1U_0201_10V K X5R  [C_0201]  151.62 105.73 0 top
CV55  0.1U_0201_10V K X5R  [C_0201]  146.41 111.19 0 top
CV60  0.1U_0201_10V K X5R  [C_0201]  146 99.34 90 top
CV61  22U_0603_6.3V6M  [C_0603]  129.01 94.06 90 bottom
CV121  1U_0201_6.3V6K  [C_0201]  180.59 129.94 0 top
CV133  0.1U_0201_10V6K  [C_0201]  127.24 119.06 270 bottom
CV158  820P_0402_25V7  [C_0402]  170.9 131.43 270 bottom
CV159  820P_0402_25V7  [C_0402]  131.9 132.92 90 bottom
CV160  10U_0402_6.3V6M  [C_0402]  169.89 132.32 90 top
CV161  1U_0201_6.3V6K  [C_0201]  169.76 137.35 90 top
CV162  1U_0201_6.3V6K  [C_0201]  169.89 127.27 90 top
CV163  1U_0201_6.3V6K  [C_0201]  156.81 128.89 270 top
CV164  1U_0201_6.3V6K  [C_0201]  156.81 126.3 90 top
CV165  0.1U_0402_25V6  [C_0402]  159.33 140.16 180 bottom
CV166  0.1U_0402_25V6  [C_0402]  166.13 140.15 0 bottom
CV167  0.1U_0402_25V6  [C_0402]  170.91 126.99 90 bottom
CV168  10U_0402_6.3V6M  [C_0402]  131.69 127.87 270 bottom
CV169  1U_0201_6.3V6K  [C_0201]  131.79 135.43 90 bottom
CV170  1U_0201_6.3V6K  [C_0201]  146.01 127.05 270 top
CV171  1U_0201_6.3V6K  [C_0201]  132.68 127.18 90 top
CV172  1U_0201_6.3V6K  [C_0201]  132.81 135.43 90 top
CV173  0.1U_0402_25V6  [C_0402]  131.92 138.4 90 bottom
CV174  0.1U_0402_25V6  [C_0402]  146.01 129.79 270 top
CV175  0.1U_0402_25V6  [C_0402]  146.01 130.78 90 top
CV190  100P_0402_50V8J  [C_0402]  161.1 90.17 180 bottom
CV198  10U_0402_6.3V6M  [C_0402]  132.36 119.45 90 bottom
CV199  10U_0402_6.3V6M  [C_0402]  130.99 116.67 270 bottom
CV200  1U_0201_6.3V6K  [C_0201]  139.03 103.64 180 top
CV201  1U_0201_6.3V6K  [C_0201]  136.51 101.1 270 top
CV202  1U_0201_6.3V6K  [C_0201]  136.77 112.09 180 top
CV203  10U_0402_6.3V6M  [C_0402]  139.61 108.81 90 top
CV204  10U_0402_6.3V6M  [C_0402]  137.1 113 180 top
CV205  1U_0201_6.3V6K  [C_0201]  138.26 113.71 0 top
CV206  1U_0201_6.3V6K  [C_0201]  137.66 105.26 270 top
CV207  0.1U_0201_10V6K  [C_0201]  138.69 100.98 180 top
CV208  0.1U_0201_10V6K  [C_0201]  139.28 105.38 270 top
CV209  12P_0402_50V8J  [C_0402]  159.7 101.34 180 bottom
CV210  12P_0402_50V8J  [C_0402]  159.7 102.61 180 bottom
CV211  0.1U_0201_10V6K  [C_0201]  150.27 99.44 180 top
CV212  1U_0201_6.3V6K  [C_0201]  150.48 101.28 270 top
CV213  4.7U 6.3V M X5R 0402  [C_0402]  151.24 101.63 270 top
CV214  0.1U_0201_10V6K  [C_0201]  151.21 103.25 0 top
CV215  0.1U_0201_10V6K  [C_0201]  144.77 109.27 0 top
CV216  4.7U 6.3V M X5R 0402  [C_0402]  150.56 96.36 180 top
CV217  4.7U_0402_6.3V6M  [C_0402]  149.15 109.15 180 top
CV218  1U_0201_6.3V6K  [C_0201]  146.61 109.84 270 top
CV219  1U_0201_6.3V6K  [C_0201]  150.27 98.81 180 top
CV220  0.1U_0201_10V6K  [C_0201]  150.86 99.4 90 top
CV221  1U_0201_6.3V6K  [C_0201]  145.02 110.91 90 top
CV222  0.1U_0201_10V6K  [C_0201]  151.43 104.45 270 top
CV223  0.1U_0201_10V K X5R  [C_0201]  172.88 96.86 90 bottom
CV311  1U_0201_6.3V6K  [C_0201]  186.25 124.35 0 top
CV312  4.7U_0402_6.3V6M  [C_0402]  187 123.59 180 top
CV313  0.1U_0201_10V K X5R  [C_0201]  192.26 123.88 270 top
CV314  1U_0201_6.3V6K  [C_0201]  126.6 119.06 270 bottom
CV315  0.1U_0402_25V6  [C_0402]  132.16 121.56 0 bottom
CV316  0.1U_0201_10V K X5R  [C_0201]  134.21 119.55 90 bottom
CV317  1U_0201_6.3V6K  [C_0201]  194.29 123.88 270 top
CV318  1U_0201_6.3V6K  [C_0201]  187.19 127.4 0 top
CV319  4.7U_0402_6.3V6M  [C_0402]  187.69 126.64 180 top
CV320  0.1U_0201_10V K X5R  [C_0201]  190.24 127.53 0 top
CV321  1U_0201_6.3V6K  [C_0201]  195.14 128.67 0 top
CV373  10U_0402_6.3V6M  [C_0402]  156.4 138.38 270 top
CV374  0.1U_0402_25V6  [C_0402]  170.91 128.77 90 bottom
CV375  0.1U_0402_25V6  [C_0402]  169.89 125.49 270 top
CV376  0.1U_0402_25V6  [C_0402]  162.65 136.9 90 top
CV377  0.1U_0402_25V6  [C_0402]  168.95 140.15 180 bottom
CV378  0.1U_0402_25V6  [C_0402]  171.03 137.94 270 bottom
CV379  0.1U_0402_25V6  [C_0402]  171.03 133.72 90 bottom
CV380  0.1U_0402_25V6  [C_0402]  156.63 140.15 0 bottom
CV381  10U_0402_6.3V6M  [C_0402]  147.43 138.01 90 bottom
CV382  0.1U_0402_25V6  [C_0402]  132.68 130.81 270 top
CV383  0.1U_0402_25V6  [C_0402]  146.01 134.72 90 top
CV384  0.1U_0402_25V6  [C_0402]  146.65 137.13 90 top
CV385  0.1U_0402_25V6  [C_0402]  142.64 140.33 0 top
CV386  0.1U_0402_25V6  [C_0402]  138.77 139.37 180 top
CV387  0.1U_0402_25V6  [C_0402]  136.28 140.29 180 top
CV388  0.1U_0402_25V6  [C_0402]  132.93 138.33 90 top
CV389  1U_0201_6.3V6K  [C_0201]  170.87 125.9 270 bottom
CV390  1U_0201_6.3V6K  [C_0201]  143.15 109.29 0 top
CV391  1U_0201_6.3V6K  [C_0201]  180.59 130.58 0 top
CV392  1U_0201_6.3V6K  [C_0201]  195.14 127.91 0 top
CV393  10U_0402_6.3V6M  [C_0402]  140.75 101.7 270 top
CV394  10U_0402_6.3V6M  [C_0402]  138.16 107.16 180 top
CV395  10U_0402_6.3V6M  [C_0402]  148.19 97.18 180 top
CV396  10U_0402_6.3V6M  [C_0402]  148.19 96.22 180 top
CWL1  0.1U_0402_16V4Z  [C_0402]  248.9 21.43 270 bottom
CWL2  0.1U_0402_16V4Z  [C_0402]  249.68 27.41 90 bottom
D1  AZ5123-02S.R7G 3P CA SOT23  [YSLC05CH_SOT23-3]  20.8 101.55 180 bottom
D6  YSLC05CH_SOT23-3  [PESD5V0U2BT_SOT23-3]  78.11 100.86 270 bottom
D7  YSLC05CH_SOT23-3  [PESD5V0U2BT_SOT23-3]  78.11 104.92 270 bottom
D21  AZ1045-04F.R7G DFN2510P10E ESD  [AZ1045-04F_DFN2510P10E-10-9]  15.48 121.16 270 bottom
D22  AZ1045-04F.R7G DFN2510P10E ESD  [AZ1045-04F_DFN2510P10E-10-9]  15.48 115.07 270 bottom
D31  AZ1045-04F_DFN2510P10E-10-9  [L05ESDL5V0NA-4_SLP2510P8-10-9]  12.79 94.82 0 top
D32  AZ1045-04F_DFN2510P10E-10-9  [L05ESDL5V0NA-4_SLP2510P8-10-9]  15.97 94.82 0 top
D33  AZ1045-04F_DFN2510P10E-10-9  [L05ESDL5V0NA-4_SLP2510P8-10-9]  9.75 94.82 0 top
DA6  -  [L03ESDL5V0CC3-2_SOT23-3]  98.48 95.84 180 bottom
DA7  -  [L03ESDL5V0CC3-2_SOT23-3]  93.87 95.89 180 bottom
DC1  BAV70W 3P C/C_SOT-323  [DAN202U_SC70-3]  91.8 35.3 0 bottom
DC3  RB751V-40_SOD323-2  [CH751H-40PT_SOD323-2]  90.41 24.44 90 bottom
DC4  RB751V-40_SOD323-2  [CH751H-40PT_SOD323-2]  92.18 24.44 90 bottom
DC6  -  [L30ESD24VC3-2_SOT23-3]  14.21 111.32 0 bottom
DG1  AZ1045-04F.R7G DFN2510P10E ESD  [AZ1045-04F_DFN2510P10E-10-9]  15.48 125.35 270 bottom
DH2  RB751V-40 SOD-323  [CH751H-40PT_SOD323-2]  15.92 140.04 90 top
DH4  RB751V-40 SOD-323  [CH751H-40PT_SOD323-2]  150.16 52.62 180 bottom
DH5  RB751V-40 SOD-323  [CH751H-40PT_SOD323-2]  150.16 50.79 180 bottom
DK2  RB751V-40 SOD-323  [CH751H-40PT_SOD323-2]  165.59 27.47 270 bottom
DL1  AZC199-02S.R7G 3P CC SOT23 ESD  [AZC199-02SPR7G_SOT23-3]  25.15 130.96 90 top
DM1  AZC199-02S.R7G 3P CC SOT23 ESD  [AZC199-02SPR7G_SOT23-3]  50.12 101.62 90 bottom
DM5  AZC199-02S.R7G  3P CC SOT23 ESD  [AZC199-02SPR7G_SOT23-3]  148.04 31.01 90 bottom
DM12  AZC099-04S_SOT-23-6-6  [YSUSB2P0-5_SOT-23-6-6]  27.6 113.8 180 bottom
DM13  AZC099-04S_SOT-23-6-6  [YSUSB2P0-5_SOT-23-6-6]  32.43 113.8 180 bottom
DM15  AZC199-02SPR7G_SOT23-3  [YSLC05CH_SOT23-3]  22.49 97.81 270 bottom
DM16  AZ1045-04F.R7G DFN2510P10E ESD  [AZ1045-04F_DFN2510P10E-10-9]  250.07 20.65 0 bottom
DT2  SOT-23-6 CEST236LC5VU-M  [AZC099-04SPR7G_SOT23-6]  144.23 32.78 270 bottom
DV1  RB751S-40 SOD-523 PANJIT  [RB751S40T1G_SOD523-2]  156.11 86.87 0 bottom
DV3  RB751S-40 SOD-523  [RB751S40T1G_SOD523-2]  172.66 92.53 270 bottom
DV4  RB751S-40 SOD-523 PANJIT  [RB751S40T1G_SOD523-2]  162.07 88.03 0 bottom
FD1  -  [FIDUCIAL_C40M80]  15.86 21.74 0 top
FD2  -  [FIDUCIAL_C40M80]  15.86 21.74 180 bottom
FD3  -  [FIDUCIAL_C40M80]  207.58 114.92 180 bottom
FD4  -  [FIDUCIAL_C40M80]  205.66 133.05 0 top
FG1  -  [AP2330W-7_SC59-3]  17.82 125.75 270 top
FG2  G5250Q1T73U SOT-23 3P POWER SWITCH  [AP2330W-7_SC59-3]  49.58 105.43 270 bottom
FG4  G5250Q1T73U SOT-23 3P POWER SWITCH  [AP2330W-7_SC59-3]  49.58 110 270 bottom
FU1  0.75A_24V_MF-MSMF075/24  [F_MF-MSMF050-2]  96.33 104.8 0 bottom
H1  HOLEA  [H_2P5N]  26.7 106.7 180 bottom
H2  HOLEA  [H_2P5X2P8N]  200.55 139.5 270 bottom
H4  HOLEA  [H_3P2]  198.8 119.6 180 bottom
H5  HOLEA  [H_3P2]  253.17 11.8 180 bottom
H6  HOLEA  [H_5P0-G]  125.34 112.32 180 bottom
H7  HOLEA  [H_5P0-G]  165.06 97.68 180 bottom
H8  HOLEA  [H_5P0-G]  94.03 81.27 180 bottom
H9  HOLEA  [H_5P0-G]  136.74 81.27 180 bottom
H10  HOLEA  [H_5P0-G]  94.03 49.47 180 bottom
H11  HOLEA  [H_5P0-G]  136.74 49.47 180 bottom
H13  HOLEA  [H_2P3-G]  13.7 102.45 180 bottom
H14  HOLEA  [H_2P3-G]  6.7 30.8 180 bottom
H15  HOLEA  [H_2P3-G]  206.05 139.5 180 bottom
H17  HOLEA  [H_2P5-G]  256.7 3.2 180 bottom
JCMOS1  0_0603_5%  [R_0603]  93.84 37.04 270 bottom
JCR  ACES_51524-0060N-001  [ACES_51524-0060N-001_6P]  261.46 20.33 254.9 bottom
JDIMM1  FOX_AS0A827-H2RB-7H  [FOX_AS0A827-H2RB-7H_260P-T]  62.5 92.78 90 bottom
JDIMM2  FOX_AS0A827-H2SB-7H  [FOX_AS0A827-H2SB-7H_260P-T]  49.18 92.78 270 bottom
JEDP  ACES_51540-03001-001  [ACES_51540-03001-001_30P]  72 99.85 0 bottom
JFAN  ACES_50271-0040N-001  [ACES_50271-0040N-001_4P]  242.92 23.81 340 bottom
JFPR  ACES_51522-00801-001  [ACES_51522-00801-001_8P]  254.25 28.15 270 bottom
JHDD  ACES_51522-00801-001  [ACES_51522-00801-001_8P]  261.75 7.65 270 bottom
JHDMI  LOTES_AHDM0064-P001A  [LOTES_AHDM0064-P001A_19P]  10 116.55 90 bottom
JHP  ACES_51524-0060N-001  [ACES_51524-0060N-001_6P]  9.7 26.1 180 bottom
JIO  ACES_51522-02601-001  [ACES_51522-02601-001_26P]  206.6 49.45 270 bottom
JKB  ACES_50690-0320N-P01  [ACES_50690-0320N-P01_32P]  204.57 33.05 180 bottom
JKBL  ACES_51575-00401-001  [ACES_51575-00401-001_4P]  214.94 18.23 180 bottom
JL33  -  [JUMP_43X79]  44.43 103.74 90 top
JLAN  SINGA_2RJ3081-1A8211F  [SINGA_2RJ3081-1A8211F_12P-T]  12.49 143.92 270 top
JP6  SHORT PADS  [SHORTPADS]  22.97 100.48 0 bottom
JPHW1  -  [JUMP_43X118]  111.28 98 180 top
JPHW9  -  [JUMP_43X79]  197.3 48.94 270 bottom
JSPK  ACES_50278-00401-001  [ACES_50278-00401-001_4P]  84.92 98.95 0 bottom
JSSD  ARGOS_NFSM0-S6715-TPH4  [ARGOS_NFSM0-S6715-TPH4_67P]  182.31 37.2 355 bottom
JTC1  SINGA_2UB3C02-002111F  [SINGA_2UB3C02-002111F_24P-T]  7.74 99.7 90 bottom
JTP1  ACES_51522-01001-001  [ACES_51522-01001-001_10P]  158.35 29.1 180 bottom
JTP2  JXT_FP202DH-004M10M  [JXT_FP202DH-004M10M_4P]  141.9 28.85 180 bottom
JWLAN  LOTES_APCI0019-P003H  [LOTES_APCI0019-P003H_67P]  219.64 21.05 270 bottom
L12  MURATA DLM0NSN900HY2D  [MURAT_DLM0NSN900HY2D_4P]  80.62 103.61 90 bottom
L13  MURATA DLM0NSN900HY2D  [MURAT_DLM0NSN900HY2D_4P]  80.37 99.8 90 bottom
L14  MURATA DLM0NSN900HY2D  [MURAT_DLM0NSN900HY2D_4P]  248.31 17.92 0 bottom
LA6  BLM15PX221SN1D  [MURAT_BLM15PX471SN1D_2P]  21.53 42.77 90 top
LED1  LTW-110DC5-C_WHITE  [LED_LTW-110DC5-C_3P]  4.7 85.91 270 bottom
